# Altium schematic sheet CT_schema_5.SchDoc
size 370 x 245 mm
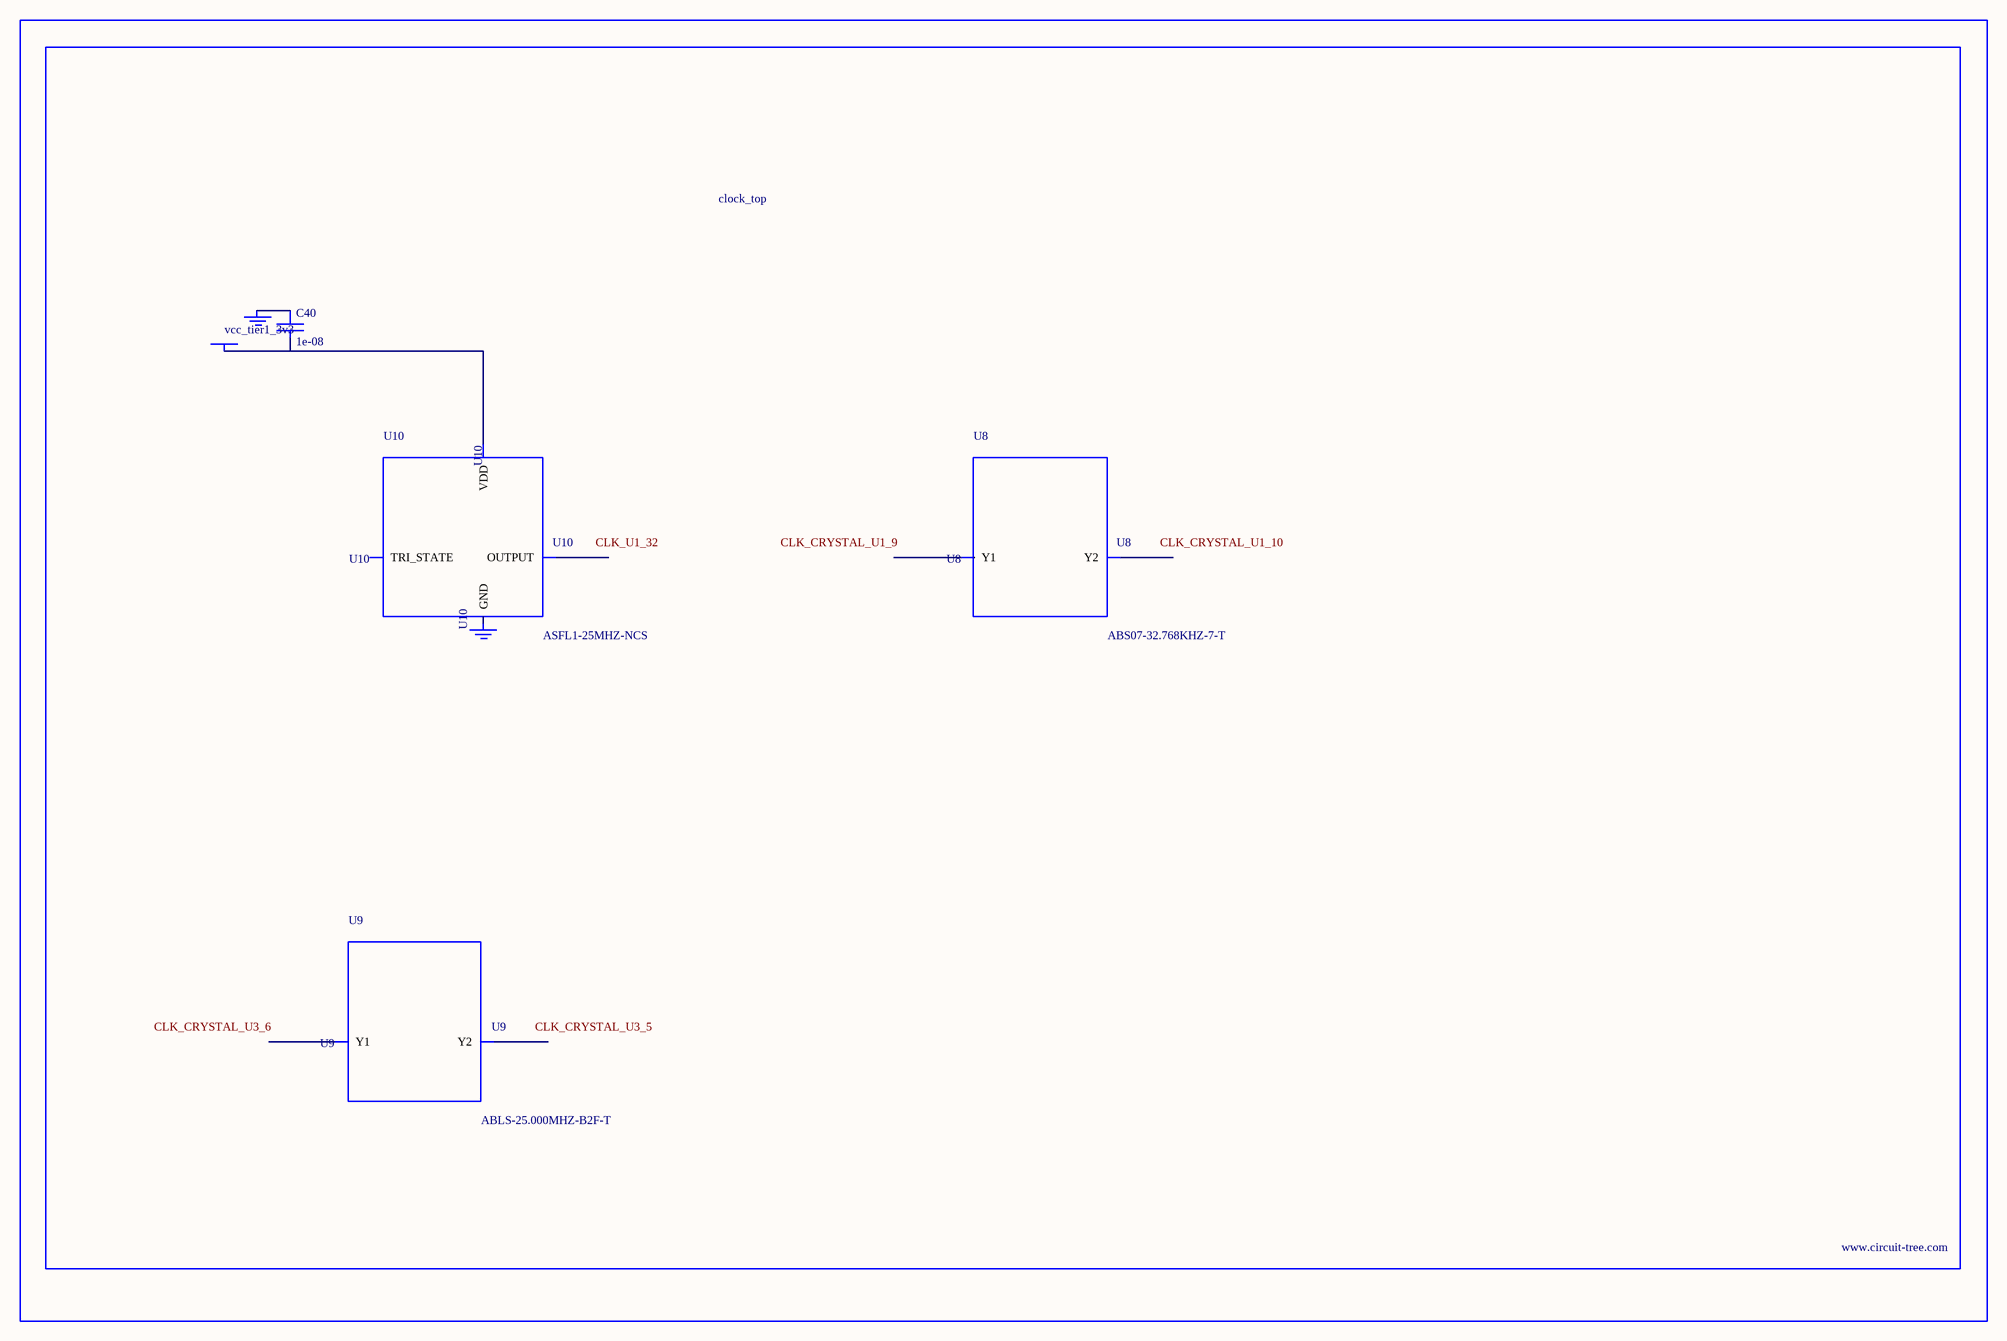
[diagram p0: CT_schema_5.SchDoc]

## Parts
BORDER4  (no value)
C40  1e-08  [C0402]
GND_INSTANCE_4_0  (no value)
GND_INSTANCE_4_1  (no value)
POWER_INSTANCE_4_0  vcc_tier1_3v3
U8  ABS07-32.768KHZ-7-T  [ABS07-32.768KHZ-7-T]
U9  ABLS-25.000MHZ-B2F-T  [ABLS-25.000MHZ-B2F-T]
U10  ASFL1-25MHZ-NCS  [ASFL1]

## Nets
NetC40_1: C40.1 GND_INSTANCE_4_0.0(GND)
NetC40_2: C40.2 POWER_INSTANCE_4_0.0(PWR) U10.4(VDD)

Not connected (* = marked no-connect by the designer): GND_INSTANCE_4_1 0(GND); U8 1(Y1) 2(Y2); U9 1(Y1) 2(Y2); U10 1(TRI_STATE) 2(GND) 3(OUTPUT)

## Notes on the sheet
- Labels drawn without touching a wire or pin: CLK_CRYSTAL_U1_9, CLK_CRYSTAL_U1_10, CLK_CRYSTAL_U3_5, CLK_CRYSTAL_U3_6, CLK_U1_32

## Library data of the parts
BORDER4 = BORDER_PAGE4
C40 = C0402C103K3RAC
GND_INSTANCE_4_0 GND_INSTANCE_4_1 = GND
POWER_INSTANCE_4_0 = PWR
